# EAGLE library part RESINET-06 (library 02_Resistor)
Resistor Network(6) 6 peaces
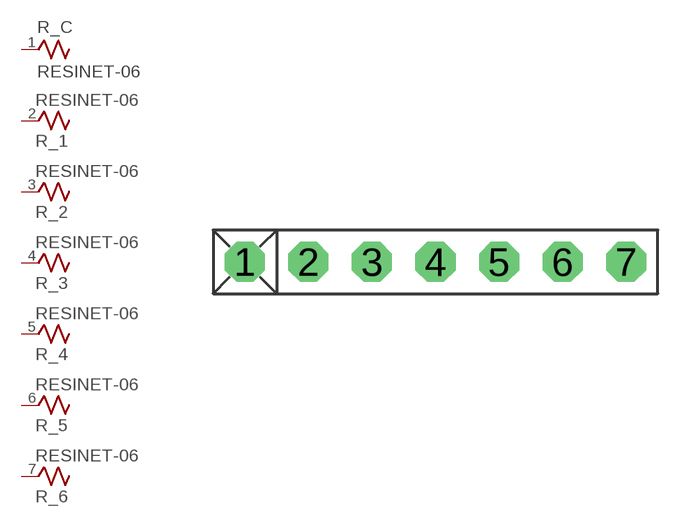
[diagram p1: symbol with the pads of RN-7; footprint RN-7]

Designator prefix R; gates _C=RESINET-COM _1=RESINET-X _2=RESINET-X _3=RESINET-X _4=RESINET-X _5=RESINET-X _6=RESINET-X

## RESINET-06  [RN-7]
1  _C:1  pas
2  _1:1  pas
3  _2:1  pas
4  _3:1  pas
5  _4:1  pas
6  _5:1  pas
7  _6:1  pas

## Footprint RN-7 (pad centres in mm)
Resistor Network(6) 6 peaces
drill 0.813 pad 1.6 octagon: 1 -7.62,0; 2 -5.08,0; 3 -2.54,0; 4 0,0; 5 2.54,0; 6 5.08,0; 7 7.62,0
